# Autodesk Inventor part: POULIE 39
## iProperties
Created: 2004-11
Part Number: POULIE 39
Document SubType Name: Modeling
Designer: Bruno
Manufacturer: Standard
Standards Organization: Custom
Author: Bruno
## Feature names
1. Base1
